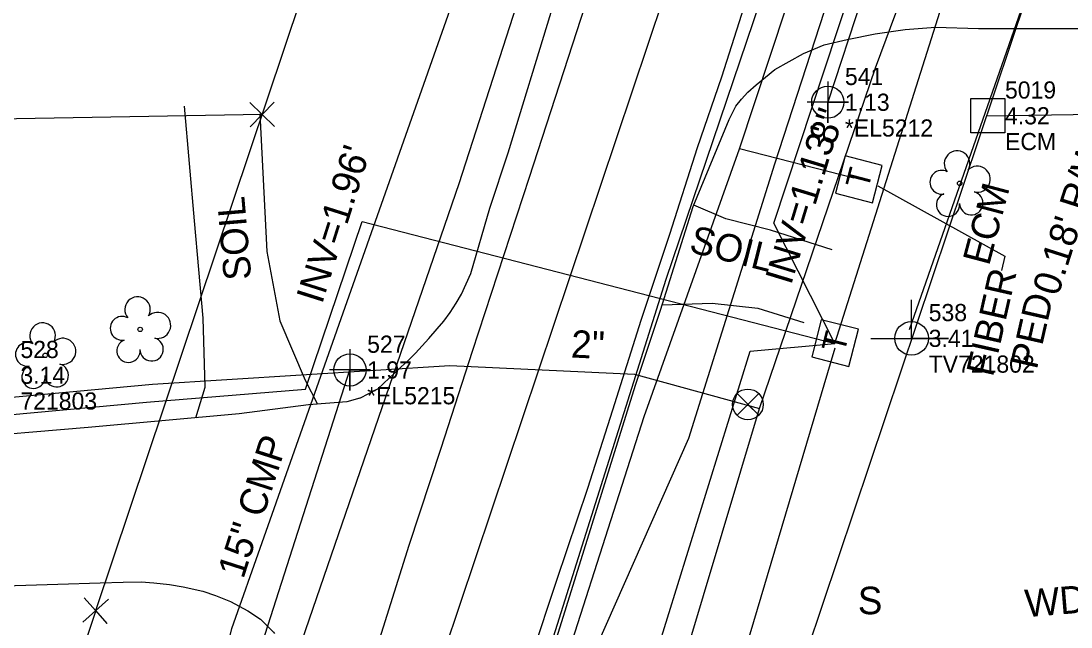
# Model space of a CAD drawing. Extents: x 3040896 to 3051146, y 687568 to 732976.
# Drawn here: x 3049876.8 to 3050029.5, y 690473.1 to 690561.3 of the extents above; entities that cross this region are included whole.
import ezdxf

# ---------------------------------------------------------------- set-up
doc = ezdxf.new("R2010")
doc.units = 0
for name, color, linetype in [('Exist Building Text', 7, 'Continuous'), ('Exist Horizontal Alignment', 7, 'Continuous'), ('Exist Other Culture Located Object Text', 7, 'Continuous'), ('Exist Property Corner CELL', 7, 'Continuous'), ('Exist Property Iron Pin Text', 7, 'Continuous'), ('Exist Property Line', 7, 'Continuous'), ('Exist Property Line Text', 7, 'Continuous'), ('Exist Property Monument CELL', 7, 'Continuous'), ('Exist Property Monument Cogo Comment', 7, 'Continuous'), ('Exist Property Monument Cogo Elevation', 7, 'Continuous'), ('Exist Property Monument Cogo Number', 7, 'Continuous'), ('Exist Right of Way Line', 7, 'Continuous'), ('Exist Roads EOP', 7, 'Continuous'), ('Exist Roads EOT', 7, 'Continuous'), ('Exist Roads Soil', 7, 'Continuous'), ('Exist Roads Soil Text', 7, 'Continuous'), ('Exist Structure Minor Pipes CMP 12 Inch', 7, 'Continuous'), ('Exist Structure Minor Pipes CMP 12 Inch Cogo Comment', 7, 'Continuous'), ('Exist Structure Minor Pipes CMP 12 Inch Cogo Elevation', 7, 'Continuous'), ('Exist Structure Minor Pipes CMP 12 Inch Cogo Number', 7, 'Continuous'), ('Exist Structure Minor Pipes CMP 12 Inch Cogo Point CELL', 7, 'Continuous'), ('Exist Structure Minor Pipes CMP 12 Inch Invert', 7, 'Continuous'), ('Exist Structure Minor Pipes CMP 15 Inch', 7, 'Continuous'), ('Exist Structure Minor Pipes CMP 15 Inch Cogo Comment', 7, 'Continuous'), ('Exist Structure Minor Pipes CMP 15 Inch Cogo Elevation', 7, 'Continuous'), ('Exist Structure Minor Pipes CMP 15 Inch Cogo Number', 7, 'Continuous'), ('Exist Structure Minor Pipes CMP 15 Inch Cogo Point CELL', 7, 'Continuous'), ('Exist Structure Minor Pipes CMP 15 Inch Invert', 7, 'Continuous'), ('Exist Structure Minor Pipes CMP 15 Inch Text', 7, 'Continuous'), ('Exist Utilities Power Joint Use Telephone CELL', 7, 'Continuous'), ('Exist Utilities Power Joint Use Telephone Cogo Comment', 7, 'Continuous'), ('Exist Utilities Power Joint Use Telephone Cogo Elevation', 7, 'Continuous'), ('Exist Utilities Power Joint Use Telephone Cogo Number', 7, 'Continuous'), ('Exist Utilities Power Pole Cogo Comment', 7, 'Continuous'), ('Exist Utilities Power Pole Cogo Elevation', 7, 'Continuous'), ('Exist Utilities Power Pole Cogo Number', 7, 'Continuous'), ('Exist Utilities Telephone Pedestal CELL', 7, 'Continuous'), ('Exist Utilities Telephone Pedestal Leader', 7, 'Continuous'), ('Exist Utilities Telephone Pedestal Text', 7, 'Continuous'), ('Exist Utilities Telephone UG Cable', 7, 'Continuous'), ('Exist Utilities Telephone UG Conduit SUE', 7, 'Continuous'), ('Exist Utilities TV UG Cable', 7, 'Continuous'), ('Exist Utilities Water UG Line', 7, 'Continuous'), ('Exist Utilities Water UG Line SUE', 7, 'Continuous'), ('Exist Utilities Water UG Line SUE Text', 7, 'Continuous'), ('Exist Utilities Water Valve CELL', 7, 'Continuous'), ('Exist Vegetation Tree CELL', 7, 'Continuous')]:
    doc.layers.add(name, color=color, linetype=linetype)

# ---------------------------------------------------------------- blocks, each defined once
blk = doc.blocks.new('EXIST UTILITIES POWER JOINT USE TELEPHONE')
at = {"layer": 'Exist Utilities Power Joint Use Telephone CELL'}
blk.add_line((0, 0), (0, 0), dxfattribs=at)
blk.add_lwpolyline([(-0.1188, 0), (0.108, -0.0008), (0, -0.0004), (0, 0.1125)], dxfattribs=at)
blk.add_circle((0, 0.0001), 0.049, dxfattribs=at)
blk = doc.blocks.new('EXIST PROPERTY MONUMENT')
at = {"layer": 'Exist Property Monument CELL'}
blk.add_line((0, 0), (0, 0), dxfattribs=at)
blk.add_lwpolyline([(-0.0499, -0.0499), (-0.0499, 0.0499), (0.0499, 0.0499), (0.0499, -0.0499), (-0.0499, -0.0499)], dxfattribs=at)

msp = doc.modelspace()

# ---------------------------------------------------------------- linework, layer by layer
at = {"layer": 'Exist Horizontal Alignment'}
msp.add_line((3049935.02, 690459.62), (3050287.69, 691510.63), dxfattribs=at)
at = {"layer": 'Exist Property Corner CELL'}
for p, q in [((3049911.84, 690547.7), (3049911.84, 690547.7)), ((3049887.62, 690475.52), (3049887.62, 690475.52))]:
    msp.add_line(p, q, dxfattribs=at)
for points in [[(3049910.1, 690545.91), (3049913.58, 690549.5), (3049911.84, 690547.7), (3049910.04, 690549.45), (3049913.63, 690545.96)], [(3049885.95, 690477.38), (3049889.29, 690473.66), (3049887.62, 690475.52), (3049889.48, 690477.19), (3049885.76, 690473.85)]]:
    msp.add_lwpolyline(points, dxfattribs=at)
at = {"layer": 'Exist Property Line'}
msp.add_line((3049911.84, 690547.7), (3049377.01, 690538.75), dxfattribs=at)
at = {"layer": 'Exist Right of Way Line'}
for p, q in [((3049887.62, 690475.52), (3050240.28, 691526.54)), ((3049982.42, 690443.71), (3050086.94, 690755.19)), ((3050017.26, 690547.53), (3050349.27, 690552.05))]:
    msp.add_line(p, q, dxfattribs=at)
msp.add_arc((3051439.28, 689954.87), 1636.68, 161.451, 171.37561, dxfattribs=at)
at = {"layer": 'Exist Roads EOP'}
for points in [[(3049926.06, 690506.43), (3049928.67, 690507.8), (3049931.99, 690510.88), (3049933.24, 690512.04), (3049934.15, 690512.97), (3049935.13, 690514.05), (3049936.1, 690515.11), (3049937.31, 690516.5), (3049938.27, 690517.66), (3049939.19, 690518.89), (3049940.09, 690520.25), (3049940.84, 690521.58), (3049941.55, 690523.06), (3049942.19, 690524.59), (3049944.97, 690534.07), (3049947.64, 690542.14), (3049953.89, 690562.6), (3049960.55, 690583.08), (3049969.52, 690609.53), (3049977.46, 690633.04), (3049984.68, 690655.11), (3049993.72, 690683.19), (3050000.98, 690704.28), (3050011.66, 690734.96)], [(3049966.16, 690508.33), (3049969.79, 690519.25), (3049974.57, 690534.32), (3049979.79, 690546.97), (3049980.75, 690548.92), (3049981.57, 690549.94), (3049982.5, 690550.97), (3049983.74, 690552.04), (3049986.44, 690554.27), (3049990.6, 690556.61), (3049993.64, 690557.87), (3049996.97, 690558.65), (3050001.02, 690559.44), (3050005.4, 690560.1), (3050009.8, 690560.43), (3050016.08, 690560.22), (3050032.46, 690560.21), (3050056.41, 690560.41), (3050080.17, 690560.8), (3050103.77, 690560.67), (3050142.65, 690561.29)], [(3049901.27, 690275.24), (3049904.75, 690291.92), (3049909.98, 690315.99), (3049918.08, 690352.04), (3049928.41, 690385.96), (3049936.64, 690413.31), (3049945.17, 690441.27), (3049954.94, 690472.39), (3049966.16, 690508.33)], [(3049926.06, 690506.43), (3049924.16, 690505.88), (3049918.57, 690505.47), (3049908.5, 690504.17), (3049886.52, 690502.17), (3049866.92, 690500.51), (3049847.34, 690498.8), (3049832.72, 690497.24), (3049811.64, 690495.22), (3049793.91, 690493.87), (3049781.4, 690493.07), (3049731.74, 690488.64), (3049701.68, 690485.65), (3049649.29, 690480.94), (3049584.92, 690476.31)], [(3049672.43, 690462.15), (3049697.46, 690463.7), (3049728.75, 690466.43), (3049757.34, 690469.71), (3049780.14, 690471.71), (3049808.95, 690474.09), (3049834.5, 690476.33), (3049856.67, 690478.21), (3049868.18, 690478.91), (3049875.9, 690479.16), (3049882.11, 690479.36), (3049888.28, 690479.55), (3049891.62, 690479.66), (3049894.24, 690479.71), (3049896.1, 690479.55), (3049898.35, 690479.34), (3049900.33, 690479), (3049903.19, 690478.35), (3049905.03, 690477.74), (3049907.26, 690476.82), (3049909.76, 690475.47), (3049911.58, 690474.27), (3049913.51, 690472.4), (3049913.65, 690472.2)]]:
    msp.add_lwpolyline(points, dxfattribs=at)
at = {"layer": 'Exist Roads EOT'}
for points in [[(3049886.83, 690327.24), (3049889.43, 690338.23), (3049892.57, 690350.46), (3049895.32, 690360.85), (3049898.32, 690371.51), (3049901.06, 690381.69), (3049904.26, 690392.29), (3049907.41, 690402.64), (3049911.23, 690415.04), (3049914.14, 690424.73), (3049916.68, 690432.53), (3049920.01, 690442.73), (3049922.91, 690452.17), (3049924.69, 690457.88), (3049933.22, 690485.05), (3049937.91, 690499.18), (3049942.46, 690513.29), (3049950.72, 690538.57), (3049957.63, 690559.77), (3049965.05, 690582.69)], [(3049983.05, 690566.87), (3049978.66, 690553.13), (3049975.14, 690542.87), (3049971.12, 690530.24), (3049966.93, 690517.72), (3049962.8, 690504.7), (3049959.2, 690493.28), (3049954.66, 690479.92), (3049951.02, 690468.96), (3049946.69, 690455.43), (3049943.14, 690444.25), (3049940.2, 690435.16), (3049936.17, 690422.5), (3049933.47, 690413.39), (3049930.42, 690403.72), (3049927.58, 690394.52), (3049924.72, 690384.74), (3049921.62, 690374.19), (3049918.35, 690362.29), (3049915.45, 690351.38), (3049912.28, 690339.34), (3049909.89, 690329.84)]]:
    msp.add_lwpolyline(points, dxfattribs=at)
at = {"layer": 'Exist Roads Soil'}
for points in [[(3049902.17, 690503.59), (3049903.56, 690508.01), (3049903.24, 690518.08), (3049902.02, 690532.26), (3049900.54, 690548.95)], [(3049911.52, 690547.8), (3049912.52, 690527.77), (3049914.42, 690517.71), (3049918.09, 690509.04), (3049919.9, 690505.56)], [(3049994.78, 690528.04), (3049985.8, 690530.9), (3049979.29, 690532.55), (3049974.65, 690534.5)], [(3049970.04, 690520.02), (3049977.31, 690520.26), (3049983.99, 690519.55), (3049990.64, 690517.43)]]:
    msp.add_lwpolyline(points, dxfattribs=at)
at = {"layer": 'Exist Structure Minor Pipes CMP 12 Inch'}
msp.add_line((3050006.63, 690587.51), (3049994.14, 690549.5), dxfattribs=at)
at = {"layer": 'Exist Structure Minor Pipes CMP 12 Inch Cogo Point CELL'}
msp.add_lwpolyline([(3049994.14, 690552.5), (3049994.14, 690546.5), (3049994.14, 690549.5), (3049997.14, 690549.5), (3049991.14, 690549.5)], dxfattribs=at)
msp.add_circle((3049994.14, 690549.5), 2.34, dxfattribs=at)
at = {"layer": 'Exist Structure Minor Pipes CMP 15 Inch'}
msp.add_line((3049909.13, 690462.37), (3049924.62, 690510.54), dxfattribs=at)
at = {"layer": 'Exist Structure Minor Pipes CMP 15 Inch Cogo Point CELL'}
msp.add_lwpolyline([(3049924.62, 690513.54), (3049924.62, 690507.54), (3049924.62, 690510.54), (3049927.62, 690510.54), (3049921.62, 690510.54)], dxfattribs=at)
msp.add_circle((3049924.62, 690510.54), 2.34, dxfattribs=at)
at = {"layer": 'Exist Utilities Telephone Pedestal CELL'}
for p, q in [((3049998.63, 690538.22), (3049998.63, 690538.22)), ((3049995.16, 690514.39), (3049995.16, 690514.39))]:
    msp.add_line(p, q, dxfattribs=at)
for points in [[(3050000.67, 690534.87), (3050002.08, 690540.28), (3049996.67, 690541.69), (3049995.26, 690536.28), (3050000.67, 690534.87)], [(3049997.23, 690511.06), (3049998.6, 690516.49), (3049993.17, 690517.85), (3049991.81, 690512.43), (3049997.23, 690511.06)]]:
    msp.add_lwpolyline(points, dxfattribs=at)
at = {"layer": 'Exist Utilities Telephone Pedestal Leader'}
msp.add_lwpolyline([(3050001.43, 690537.34), (3050019.92, 690527.1), (3050019.44, 690524.99)], dxfattribs=at)
at = {"layer": 'Exist Utilities Telephone UG Cable'}
for points in [[(3049807.96, 690042.66), (3049866.08, 690051.97), (3049875.91, 690126.8), (3049889.86, 690222.55), (3049901.28, 690281.37), (3049920.46, 690362.46), (3049941.78, 690432.13), (3049970.63, 690523.76), (3050041.1, 690731.76), (3050122.9, 690978.04), (3050141.1, 690973.41), (3050146.31, 690975.95)], [(3049995.16, 690514.39), (3050028.57, 690619.91), (3050064.4, 690724.38), (3050089.6, 690805.71), (3050135.5, 690948.15), (3050146.31, 690975.95)], [(3049807.96, 690042.66), (3049822.09, 690048.55), (3049831.18, 690105.41), (3049865.1, 690270.6), (3049906.44, 690438.6), (3049940.53, 690537.69), (3050008.51, 690748.42), (3050002.98, 690756.9)], [(3049834.32, 690207.14), (3049846.67, 690212.16), (3049874.63, 690341.66), (3049907.44, 690472.92), (3050004.25, 690747.49), (3050002.98, 690756.9)], [(3049995.16, 690514.39), (3049986.29, 690531.91), (3050006.69, 690593.75), (3050031.95, 690589.62), (3050139.11, 690590.89), (3050200.52, 690592.14), (3050202.73, 690596.2), (3050212.64, 690596.09), (3050243.74, 690596.65)], [(3049584.92, 690477.31), (3049895.01, 690505.85), (3049918.15, 690507.75), (3049926.4, 690532.16), (3049995.16, 690514.39)], [(3049897.5, 690051.27), (3049891.41, 690068.79), (3049897.38, 690127.51), (3049912.31, 690206.21), (3049938.46, 690311.14), (3049963.83, 690408.17), (3049995.22, 690513.74)], [(3049948.27, 690401.68), (3049982.83, 690513.29), (3049995.16, 690514.39)]]:
    msp.add_lwpolyline(points, dxfattribs=at)
at = {"layer": 'Exist Utilities Telephone UG Conduit SUE'}
for points in [[(3049997.93, 690538.44), (3049981.31, 690542.74), (3050001.73, 690604.48), (3050022.69, 690664.7)], [(3049873.92, 690061.87), (3049878.18, 690106.84), (3049881.61, 690136.87), (3049889.91, 690175.34), (3049895.72, 690207.99), (3049902.52, 690248.49), (3049915.94, 690301.89), (3049921.05, 690335.96), (3049925.79, 690362.07), (3049941.95, 690408.24), (3049955.2, 690458.33), (3049973.93, 690500.61), (3049986.46, 690540.55), (3050006.73, 690602.94), (3050020.77, 690640.09), (3050025.62, 690664.26)], [(3049858.43, 689927.4), (3049862.17, 689984.86), (3049869.26, 690049.55), (3049874.76, 690106.34), (3049878.69, 690136.76), (3049889.12, 690203.09), (3049896.95, 690249.7), (3049912.69, 690320.73), (3049912.69, 690320.73), (3049936.08, 690405.96), (3049967.44, 690503.77), (3049981.31, 690542.74)]]:
    msp.add_lwpolyline(points, dxfattribs=at)
at = {"layer": 'Exist Utilities TV UG Cable'}
msp.add_lwpolyline([(3050006.05, 690516.43), (3050035.05, 690599.4), (3050209.46, 690599.73), (3050244.95, 690600.04)], dxfattribs=at)
at = {"layer": 'Exist Utilities Water UG Line'}
msp.add_lwpolyline([(3049580.62, 690479.33), (3049895.89, 690508.46)], dxfattribs=at)
at = {"layer": 'Exist Utilities Water UG Line SUE'}
for points in [[(3049984.23, 690504.92), (3050001.1, 690554.51), (3050013.86, 690588.84), (3050026.83, 690585.23)], [(3049895.89, 690508.46), (3049939.16, 690511.2), (3049966.04, 690509.91), (3049984.23, 690504.92)], [(3049947.53, 690372.09), (3049973.34, 690468.66), (3049984.23, 690504.92)]]:
    msp.add_lwpolyline(points, dxfattribs=at)
at = {"layer": 'Exist Utilities Water Valve CELL'}
msp.add_lwpolyline([(3049984.1, 690507.11), (3049980.95, 690503.96), (3049982.52, 690505.53), (3049984.1, 690503.96), (3049980.95, 690507.11)], dxfattribs=at)
msp.add_circle((3049982.52, 690505.53), 2.23, dxfattribs=at)
at = {"layer": 'Exist Vegetation Tree CELL'}
for p, q in [((3050013.34, 690537.7), (3050013.34, 690537.7)), ((3049894.09, 690516.44), (3049894.09, 690516.44)), ((3049880.28, 690512.66), (3049880.28, 690512.66))]:
    msp.add_line(p, q, dxfattribs=at)
for centre in [(3050013.34, 690537.7), (3049894.09, 690516.44), (3049880.28, 690512.66)]:
    msp.add_circle(centre, 0.326, dxfattribs=at)
for centre, radius, start, end in [((3050012.96, 690540.57), 1.86, 330.1651, 219.7134), ((3050010.74, 690537.85), 1.73, 62.6636, 279.3457), ((3050015.89, 690538.29), 1.9, 257.1011, 134.1999), ((3050011.64, 690534.58), 1.69, 111.5671, 6.231), ((3050015.02, 690534.8), 1.7, 181.2822, 74.56), ((3049893.71, 690519.32), 1.86, 330.1651, 219.7134), ((3049891.48, 690516.6), 1.73, 62.6636, 279.3457), ((3049896.64, 690517.03), 1.9, 257.1011, 134.1999), ((3049879.9, 690515.53), 1.86, 330.1651, 219.7134), ((3049882.83, 690513.25), 1.9, 257.1011, 134.1999), ((3049892.39, 690513.32), 1.69, 111.5671, 6.231), ((3049895.76, 690513.54), 1.7, 181.2822, 74.56), ((3049877.68, 690512.81), 1.73, 62.6636, 279.3457), ((3049878.58, 690509.54), 1.69, 111.5671, 6.231), ((3049881.96, 690509.76), 1.7, 181.2822, 74.56)]:
    msp.add_arc(centre, radius, start, end, dxfattribs=at)

# ---------------------------------------------------------------- block references
at = {"layer": 'Exist Property Monument CELL', "xscale": 50, "yscale": 50}
msp.add_blockref('EXIST PROPERTY MONUMENT', (3050017.43, 690547.53), dxfattribs=at)
at = {"layer": 'Exist Utilities Power Joint Use Telephone CELL', "xscale": 50, "yscale": 50}
msp.add_blockref('EXIST UTILITIES POWER JOINT USE TELEPHONE', (3050006.33, 690515.14), dxfattribs=at)

# ---------------------------------------------------------------- texts
at = {"layer": 'Exist Building Text'}
msp.add_text('S', height=4, rotation=0, dxfattribs=at).set_placement((3049998.52, 690474.99))
at = {"layer": 'Exist Other Culture Located Object Text'}
msp.add_text('WD POST', height=4, rotation=4.671, dxfattribs=at).set_placement((3050022.99, 690474.55))
at = {"layer": 'Exist Property Iron Pin Text'}
msp.add_text('ECM', height=4, rotation=75.1482, dxfattribs=at).set_placement((3050017.6, 690525.58))
at = {"layer": 'Exist Property Line Text'}
msp.add_text("0.18' R/W", height=4, rotation=72.3346, dxfattribs=at).set_placement((3050027.65, 690521.14))
at = {"layer": 'Exist Property Monument Cogo Comment'}
msp.add_text('ECM', height=2.5, dxfattribs=at).set_placement((3050019.93, 690542.53))
at = {"layer": 'Exist Property Monument Cogo Elevation'}
msp.add_text('4.32', height=2.5, dxfattribs=at).set_placement((3050019.93, 690546.28))
at = {"layer": 'Exist Property Monument Cogo Number'}
msp.add_text('5019', height=2.5, dxfattribs=at).set_placement((3050019.93, 690550.03))
at = {"layer": 'Exist Roads Soil Text'}
for rotation, p in [(94.9375, (3049910.29, 690523.77)), (345.8276, (3049973.8, 690527.75))]:
    msp.add_text('SOIL', height=4, rotation=rotation, dxfattribs=at).set_placement(p)
at = {"layer": 'Exist Structure Minor Pipes CMP 12 Inch Cogo Comment'}
msp.add_text('*EL5212', height=2.5, dxfattribs=at).set_placement((3049996.64, 690544.5))
at = {"layer": 'Exist Structure Minor Pipes CMP 12 Inch Cogo Elevation'}
msp.add_text('1.13', height=2.5, dxfattribs=at).set_placement((3049996.64, 690548.25))
at = {"layer": 'Exist Structure Minor Pipes CMP 12 Inch Cogo Number'}
msp.add_text('541', height=2.5, dxfattribs=at).set_placement((3049996.64, 690552))
at = {"layer": 'Exist Structure Minor Pipes CMP 12 Inch Invert'}
msp.add_text("INV=1.13'", height=4, rotation=73.1149, dxfattribs=at).set_placement((3049988.8, 690522.77))
at = {"layer": 'Exist Structure Minor Pipes CMP 15 Inch Cogo Comment'}
msp.add_text('*EL5215', height=2.5, dxfattribs=at).set_placement((3049927.12, 690505.54))
at = {"layer": 'Exist Structure Minor Pipes CMP 15 Inch Cogo Elevation'}
msp.add_text('1.97', height=2.5, dxfattribs=at).set_placement((3049927.12, 690509.29))
at = {"layer": 'Exist Structure Minor Pipes CMP 15 Inch Cogo Number'}
msp.add_text('527', height=2.5, dxfattribs=at).set_placement((3049927.12, 690513.04))
at = {"layer": 'Exist Structure Minor Pipes CMP 15 Inch Invert'}
msp.add_text("INV=1.96'", height=4, rotation=72.4605, dxfattribs=at).set_placement((3049920.55, 690520))
at = {"layer": 'Exist Structure Minor Pipes CMP 15 Inch Text'}
msp.add_text('15" CMP', height=4, rotation=72.1781, dxfattribs=at).set_placement((3049909.1, 690480.01))
at = {"layer": 'Exist Utilities Power Joint Use Telephone Cogo Comment'}
msp.add_text('TV721802', height=2.5, dxfattribs=at).set_placement((3050008.83, 690510.14))
at = {"layer": 'Exist Utilities Power Joint Use Telephone Cogo Elevation'}
msp.add_text('3.41', height=2.5, dxfattribs=at).set_placement((3050008.83, 690513.89))
at = {"layer": 'Exist Utilities Power Joint Use Telephone Cogo Number'}
msp.add_text('538', height=2.5, dxfattribs=at).set_placement((3050008.83, 690517.64))
at = {"layer": 'Exist Utilities Power Pole Cogo Comment'}
msp.add_text('721803', height=2.5, dxfattribs=at).set_placement((3049876.67, 690504.77))
at = {"layer": 'Exist Utilities Power Pole Cogo Elevation'}
msp.add_text('3.14', height=2.5, dxfattribs=at).set_placement((3049876.67, 690508.52))
at = {"layer": 'Exist Utilities Power Pole Cogo Number'}
msp.add_text('528', height=2.5, dxfattribs=at).set_placement((3049876.67, 690512.27))
at = {"layer": 'Exist Utilities Telephone Pedestal CELL'}
for rotation, p in [(75.3915, (3050000, 690536.69)), (75.896, (3049996.54, 690512.88))]:
    msp.add_text('T', height=3.42, rotation=rotation, dxfattribs=at).set_placement(p)
at = {"layer": 'Exist Utilities Telephone Pedestal Text'}
for s, p in [('FIBER', (3050018.16, 690509.41)), ('PED', (3050024.55, 690510.48))]:
    msp.add_text(s, height=4, rotation=77.2166, dxfattribs=at).set_placement(p)
at = {"layer": 'Exist Utilities Water UG Line SUE Text'}
for s, rotation, p in [('8"', 71.2188, (3049995.11, 690543.1)), ('2"', 357.2533, (3049956.72, 690512.36))]:
    msp.add_text(s, height=4, rotation=rotation, dxfattribs=at).set_placement(p)

doc.saveas('drawing.dxf')
